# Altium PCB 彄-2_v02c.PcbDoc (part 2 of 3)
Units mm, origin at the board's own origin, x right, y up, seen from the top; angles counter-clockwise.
Board outline 115 x 70 mm, 4 copper layers (Top Layer, Mid-Layer 1, Mid-Layer 2, Bottom Layer), stack 1.49 mm thick; 312 components, 169 nets, 916 pads, 492 vias.
Unrouted connection lines stored in the file: 1.
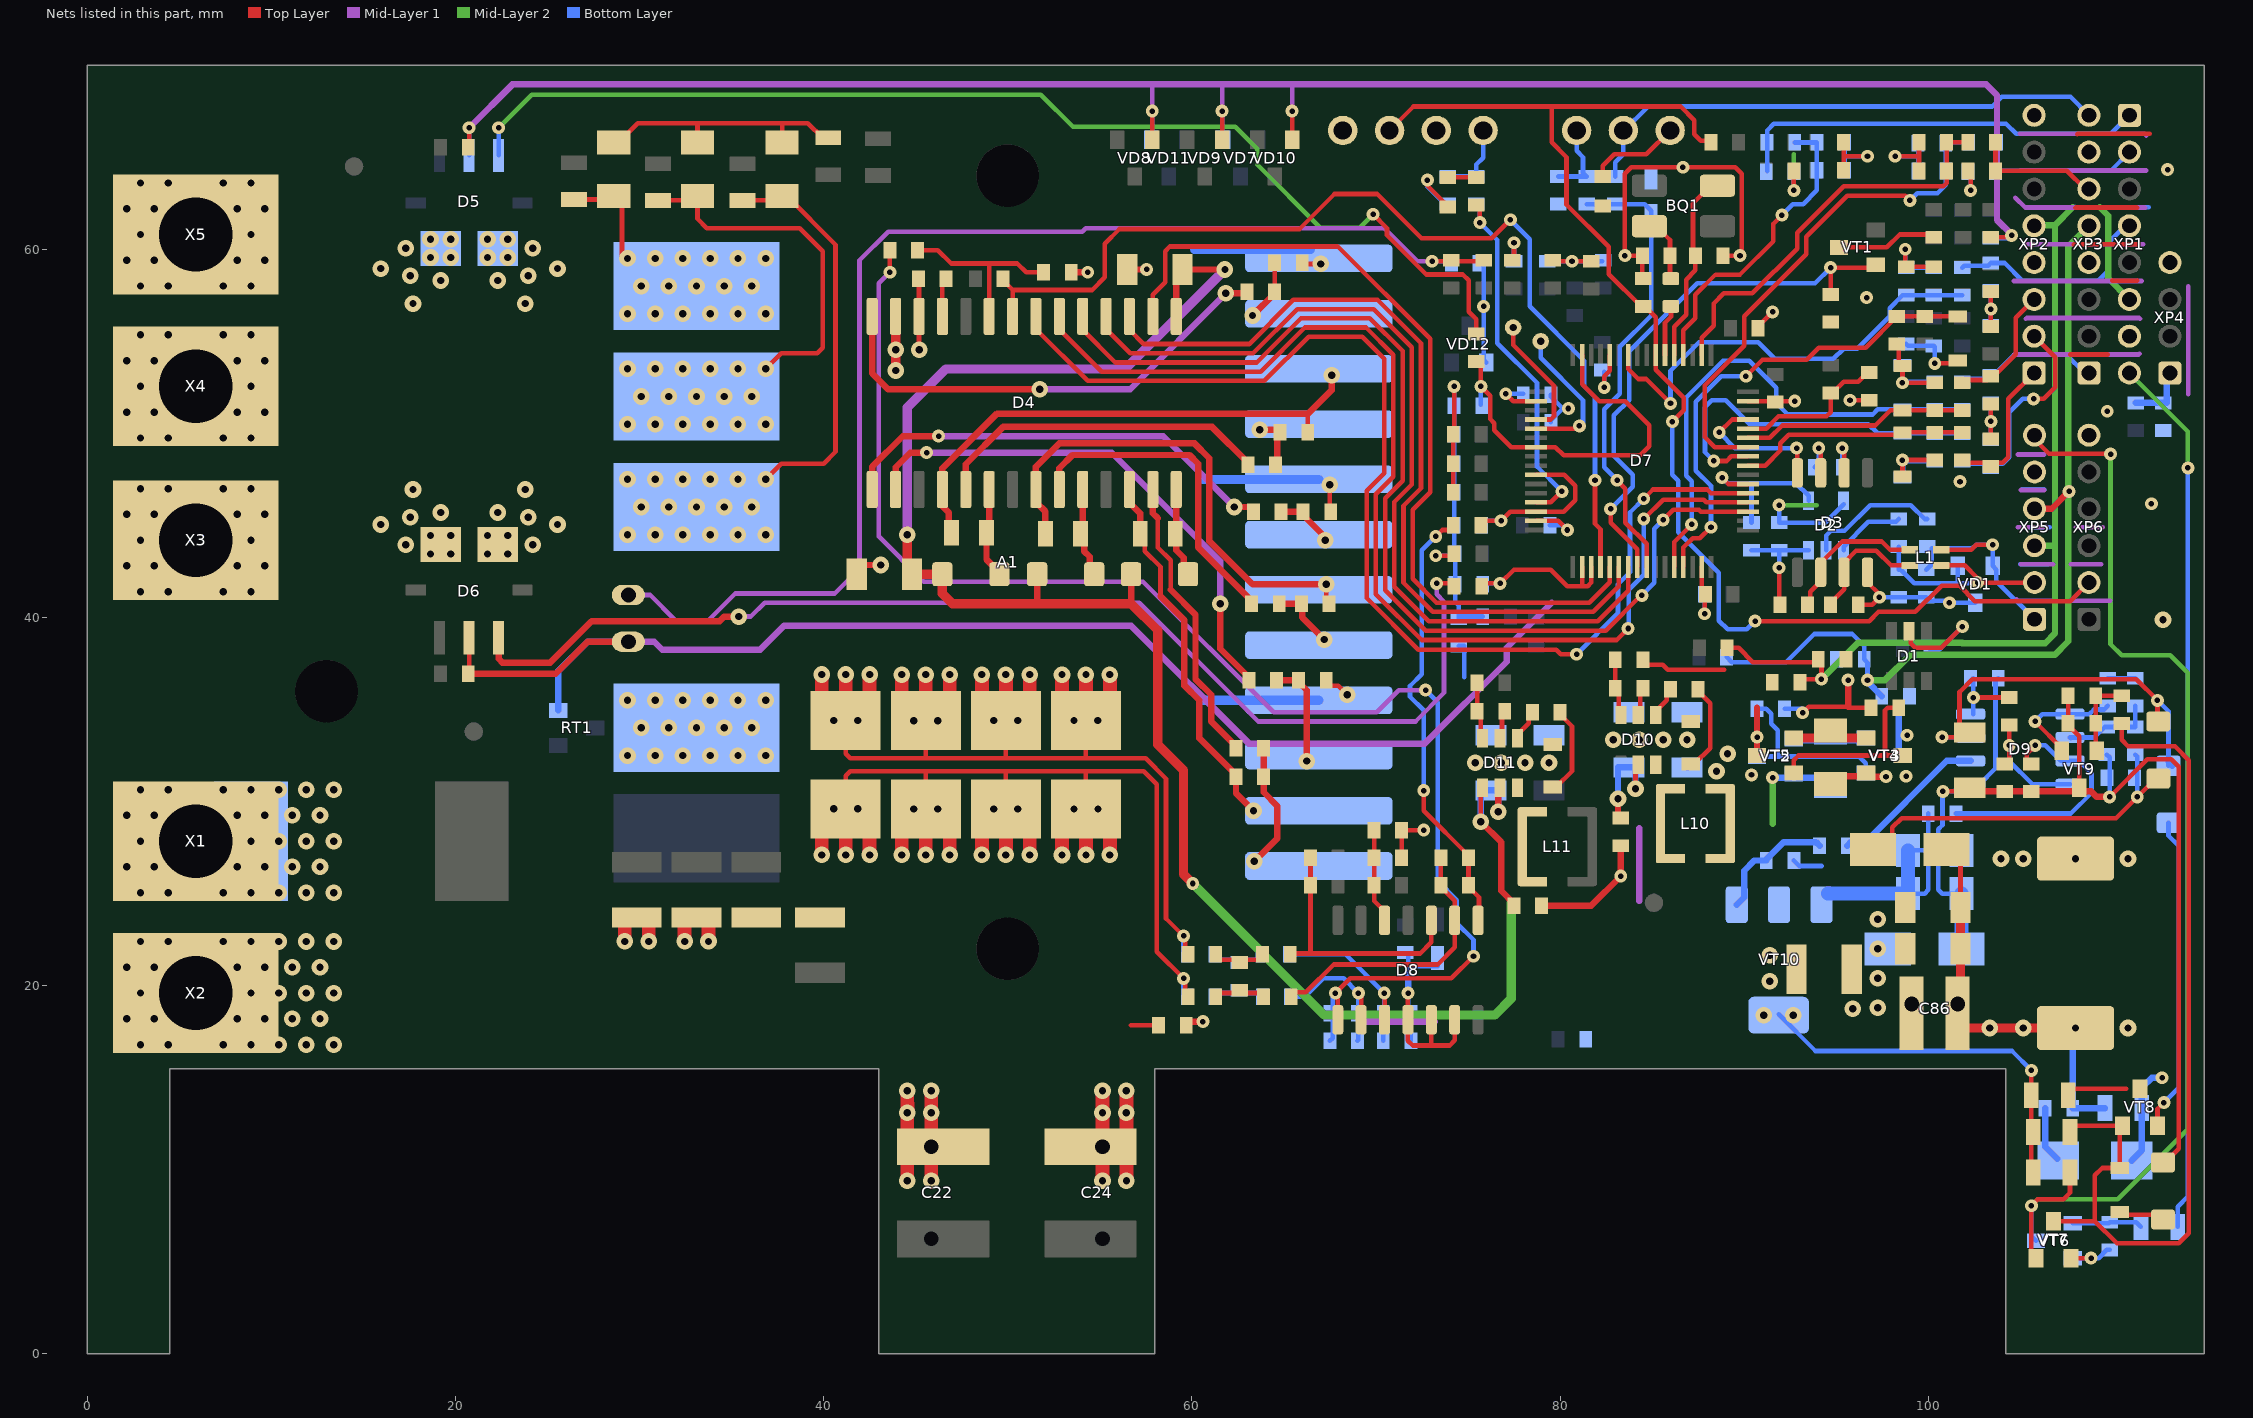
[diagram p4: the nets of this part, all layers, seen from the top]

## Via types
v1: diameter 0.9, hole 0.4, Top Layer to Bottom Layer, 233 vias
v2: diameter 0.7, hole 0.3, Top Layer to Bottom Layer, tented both sides, 184 vias
v3: diameter 0.9, hole 0.4, Top Layer to Bottom Layer, tented both sides, 50 vias
v4: diameter 0.9, hole 0.4, Top Layer to Bottom Layer, tented bottom, 25 vias

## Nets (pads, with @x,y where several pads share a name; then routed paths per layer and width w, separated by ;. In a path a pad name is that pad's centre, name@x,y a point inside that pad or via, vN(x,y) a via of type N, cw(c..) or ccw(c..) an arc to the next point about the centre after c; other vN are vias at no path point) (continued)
5V: C2.2 C3.2 C84.2 D2.5 D3.3 L10.2 R64.1 R65.1 R66.1 R67.1 R68.1 R69.1 R70.1 R91.1 R92.1 R93.1 R94.1 R95.1 R97.1 R126.1 VT3.2 | length 31.2
  Top Layer w0.25: R126.1@84.5,37.7 84.775,37.425 85.575,37.425 85.85,37.15 88.925,37.15 ; v2(92.7,63.2) R64.1@92.7,64.25 ; D3.3@94.16,47.85 v2@94.16,49.19 ; v2(102.3,63.2) R68.1@102.3,64.25 ; R94.1@103.4,49.7 v2(103.4,50.65) R91.1@103.4,51.6 ; R93.1@103.4,55.8 v2(103.4,56.75) R67.1@103.4,57.7
  Top Layer w0.35: R97.1@94.775,30.95 95.2,31.375 96.45,31.375 VT3.2@96.625,31.55 ; VT3.2@96.775,31.35 96.777,31.352 v2(97.705,31.352)
  Mid-Layer 2 w0.25: v2(91.9,46.1) 93.95,46.1 ; v2(92.7,63.2) 92.7,65.15
  Bottom Layer w0.25: v2(91.9,46.1) C2.2@91.9,45.15 94.4,45.15 D2.5@95.4,46.15 ; v2(92.7,63.2) R65.1@92.7,64.2 ; C3.2@93.83,48.15 94.05,48.37 v2(94.05,49.2) ; v2(102.3,63.2) R69.1@102.3,64.2 ; R92.1@103.4,49.65 v2(103.4,50.65) R95.1@103.4,51.65 ; R70.1@103.4,55.85 v2(103.4,56.75) R66.1@103.4,57.75
  Bottom Layer w0.35: C84.2@86.9,31.85 C84.2@86.9,32.2
  other v3: 88.5,31.65 89.1,32.6
12V: C9.2 C10.2 C86.1 C87.2 C88.2 D4.1 L8.1 L9.1 L12.2 R96.1 R128.1 R129.1 VD2.2 VD3.2 VD4.2 VD25.2 VT2.2 | length 128.9
  Top Layer w0.25: VD25.2@101,27.4 101.75,26.65 C87.2@101.75,24.25
  Top Layer w0.35: 51.6,40.75 VD3.2@51.6,42.35 ; 56.7,40.75 VD2.2@56.7,42.35 ; C9.2@59.15,59 C9.2@59.15,58.9 ; D4.1@59.155,56.35 59.155,58.895 C9.2@59.15,58.9 ; v3(61.8,58.9) C9.2@59.5,58.9 C9.2@59.15,58.9 ; L9.1@79,24.35 81.7,24.35 v2(83.3,25.95) L8.1@83.3,27.6
  Top Layer w0.5: C10.2@44.55,42.35 v3(44.55,44.5) ; C10.2@44.8,42.35 VD4.2@46.45,42.35 46.45,41.3 47,40.75 51.6,40.75 56.7,40.75 58.15,39.3 58.15,33.1 59.55,31.7 59.55,26.05 v2(60.05,25.55) ; C87.2@101.75,24.25 C88.2@101.75,22 101.75,18.65 101.6,18.8 C86.1@101.6,18.5 101.6,17.7 v3(103.35,17.7) v3(105.15,17.7) v4(108,17.7)
  Mid-Layer 1 w0.5: v3(44.55,44.5) 44.55,51.4 46.65,53.5 56.4,53.5 v3(61.8,58.9)
  Mid-Layer 2 w0.35: 91.55,28.8 v2(91.55,31.3)
  Mid-Layer 2 w0.5: v2(60.05,25.55) 67.2,18.4 76.45,18.4 77.35,19.3 77.35,24.5
  Bottom Layer w0.35: v2(91.55,31.3) 92.5,31.3 VT2.2@92.7,31.5 92.9,31.3 94.325,31.3 R96.1@94.775,30.85 ; v4@107.85,17.55 R128.1@107.85,13.35 R129.1@109.6,13.35
  other v3: 110.85,17.7
+5VO: C71.2 L6.2 R107.2 XP1.6 XP2.5 XP5.3 | length 54.2
  Top Layer w0.25: R107.2@89.075,38.35 89.7,38.35 90.475,37.575 93.775,37.575 C71.2@93.925,37.725 ; L6.2@93.025,36.475 93.2,36.65 v2(94.2,36.65) 94.2,37.55 C71.2@94.025,37.725
  Mid-Layer 2 w0.25: 107.85,62.275 109.325,62.275
  Mid-Layer 2 w0.35: v2(94.2,36.65) 96.165,38.615 101.835,38.615 101.85,38.6 106.35,38.6 106.885,39.135 106.885,43.9 ; XP5.3@105.775,43.9 106.885,43.9 ; XP2.5@105.785,61.31 106.885,61.31 ; 107.85,62.275 106.885,61.31 ; 109.325,62.275 109.775,61.825 109.775,58.425 XP1.6@110.925,57.275 ; 106.885,43.9 106.885,61.31
+12VO: C70.2 L5.2 R106.2 XP3.5 XP5.4 | length 48.7
  Top Layer w0.35: XP5.4@105.775,45.9 106.7,45.9 v2(107.65,46.85)
  Mid-Layer 2 w0.35: v2(96.7,36.6) 97.65,36.6 99.016,37.966 106.866,37.966 107.6,38.7 107.6,60.15 XP3.5@108.725,61.275
  Bottom Layer w0.25: R106.2@89.05,37.85 89.325,37.575 92.275,37.575 93.8,39.1 95.875,39.1 96.525,38.45 C70.2@96.525,37.725 96.7,37.55 v2(96.7,36.6) v2@96.7,36.5
  Bottom Layer w0.35: v2@96.7,36.5 L5.2@97.475,35.725
\FAULT: D4.8 D7.36 R4.2 | length 54.8
  Top Layer w0.25: R4.2@49.75,58.4 49.75,58.3 50.265,57.785 ; D4.8@50.265,56.35 50.265,57.785 ; v2(77.3,61.6) 76.3,60.6 72.475,60.6 70.075,63 67.75,63 65.85,61.1 56.075,61.1 55.275,60.3 55.275,58.475 54.585,57.785 50.265,57.785 ; v2(81.9,47.45) 81.9,45.1 82.2,44.8 D7.36@82.2,42.75
  Bottom Layer w0.25: v2(77.3,61.6) 78.35,60.55 78.35,56.9 81.3,53.95 81.3,52.557 81.9,51.957 v2(81.9,47.45)
\P_ON: R110.1 VT6.3 VT7.1 XP5.6 | length 63.4
  Top Layer w0.25: XP5.6@105.55,49.9 106.56,48.89 109.885,48.89 v2(109.9,48.875) ; VT7.1@105.85,5.2 105.6,5.45 v2(105.6,8.05) 105.95,8.4 107.35,8.4 107.7,8.75 R110.1@107.7,9.85
  Mid-Layer 2 w0.25: v2(105.6,8.05) 105.95,8.4 110.3,8.4 114.1,12.2 114.1,37 113.15,37.95 110.5,37.95 109.9,38.55 v2(109.9,48.875)
  Bottom Layer w0.25: v2(105.6,8.05) 105.6,6.4 VT6.3@105.85,6.15
\RESET: C37.2 D7.7 R30.1 XP6.2 XV10.1 | length 73.5
  Top Layer w0.25: XV10.1@70.74,66.45 72.04,67.75 79.55,67.75 ; C37.2@84.525,56.9 84.4,56.9 82.65,58.65 82.65,60.125 80.35,62.425 80.35,65 79.55,65.8 79.55,67.75 ; C37.2@84.6,56.9 85.2,56.3 D7.7@85.2,54.25 85.2,53.495 85.2,53.45 86.725,51.925 86.725,51.265 v2(86.1,50.64) 86.08,50.62 v2@86.08,50.64 ; R30.1@88.2,65.9 87.65,65.9 87.3,66.25 87.3,67 86.55,67.75 79.55,67.75 ; v2(90.6,39.8) 96.8,39.8 97.3,40.3 99.3,40.3 100.725,41.725 101.7,41.725 102.535,40.89 107.715,40.89 XP6.2@108.725,41.9
  Bottom Layer w0.25: v2(86.1,50.64) 86.1,47.743 86.425,47.418 86.425,44.625 88.625,42.425 88.625,39.825 89.1,39.35 90.15,39.35 v2(90.6,39.8)
\TMotor-PLUP: D7.40 R63.2 VT1.1 | length 30.4
  Top Layer w0.25: v2(82.75,45.9) 82.75,45.15 84.2,43.7 D7.40@84.2,42.75 ; R63.2@94.7,57.55 v2(94.7,59) 97,59 VT1.1@97.15,59.15
  Bottom Layer w0.25: v2(82.75,45.9) 83.95,47.1 83.95,47.75 82.925,48.775 82.925,50.975 83.75,51.8 83.75,54.45 87.45,58.15 93.85,58.15 v2(94.7,59)
A(+)LED: R27.1 XP3.8 XV8.1 | length 29.2
  Bottom Layer w0.25: R27.1@83,63.95 83,64.725 83.44,65.165 XV8.1@83.44,66.4 ; XV8.1@83.44,66.45 XV8.1@83.44,66.4 ; XP3.8@108.725,67.275 107.725,68.275 104,68.275 103.475,67.75 84.79,67.75 XV8.1@83.44,66.4
ABRAKE-IN: R66.2 R75.1 XP1.4 | length 11.5
  Bottom Layer w0.25: R75.1@101.85,59 101.95,59.1 103.25,59.1 R66.2@103.4,59.25 104.15,59.25 105.115,58.285 109.235,58.285 109.725,58.775 109.725,60.3 XP1.4@110.7,61.275
AGND: C15.1 C16.1 C21.1 C23.1 C33.1 C34.1 C41.2 C42.2 C45.1 C47.1 C48.2 C49.2 C50.2 C51.2 C52.2 C53.2 C54.1 C55.1 C63.1 C64.2 D5.2 D6.2 D7.12 D8.11 D8.12 D8.13 L4.2 R39.1 R43.1 R57.1 R58.1 R59.1 R60.1 R61.1 R62.1 R98.1 RT1.2 RT2.2 VD6.2 VD7.1 VD8.1 VD9.1 VD10.1 VD11.1 VD12.1 | length 237.6
  Top Layer w0.25: C21.1@20.75,37 D6.2@20.75,38.9 ; C16.1@20.75,65.6 v2(20.75,66.6) ; VD8.1@57.85,65.95 v2(57.85,67.5) ; VD9.1@61.65,65.95 v2(61.65,67.5) ; VD10.1@65.45,65.95 v2(65.45,67.5) ; C41.2@71.4,26.95 R39.1@71.4,28.45 v2(72.6,28.45) ; v2@71.74,19.59 D8.11@71.74,18.15 71.74,17.01 72,16.75 73,16.75 ; D8.12@73.01,18.15 73.01,16.76 73,16.75 ; v2(73.25,43.35) R61.1@74.15,43.35 ; R57.1@74.2,46.85 R59.1@74.2,48.35 R98.1@74.2,49.95 74.25,50 v2(74.25,52.55) ; D8.13@74.28,18.15 74.28,17.03 74,16.75 73,16.75 ; R60.1@77.5,59.4 v2(77.5,60.35) ; R62.1@79.6,59.4 79.65,59.35 v2(80.65,59.35) R58.1@81.7,59.35 ; v2(82.4,52.5) 82.4,53.1 82.7,53.4 D7.12@82.7,54.25 ; C55.1@103.4,60.65 104.467,60.65 v2@104.55,60.733
  Top Layer w0.35: C21.1@20.7,36.95 25.45,36.95 27.18,38.68 RT2.2@29.4,38.68
  Mid-Layer 1 w0.25: v2(57.85,67.5) 57.85,68.95 ; v2(61.65,67.5) 61.65,68.95 ; v2(65.45,67.5) 65.45,68.95
  Mid-Layer 1 w0.35: v2(20.75,66.6) 23.1,68.95 57.85,68.95 61.65,68.95 65.45,68.95 103.15,68.95 103.735,68.365 103.735,61.59 104.53,60.795 v2(104.53,60.753) ; RT2.2@29.4,38.68 30.8,38.68 31.23,38.25 36.55,38.25 37.85,39.55 56.703,39.55 63.103,33.15 72.65,33.15 77.1,37.6 77.1,38.35 79.55,40.8
  Bottom Layer w0.25: D5.2@20.75,65.1 v2(20.75,66.6) ; VD11.1@57.85,65.95 v2(57.85,67.5) ; VD7.1@61.65,65.95 v2(61.65,67.5) ; v2(71.75,19.6) 71.75,18.65 C42.2@71.9,18.5 R43.1@71.9,17 ; C47.1@71.75,21.65 71.75,21.05 VD6.2@73.35,21.05 ; v2(73.25,43.35) C52.2@74.2,43.35 ; C52.2@74.25,43.6 C64.2@74.25,49.85 ; C64.2@74.25,49.95 C15.1@74.25,51.5 v2(74.25,52.55) ; C52.2@74.3,43.35 74.3,40.85 74.5,40.65 L4.2@74.5,39.95 74.6,40.05 C34.1@75.8,40.05 ; L4.2@74.5,39.925 L4.2@74.513,39.938 ; VD12.1@75.825,54.025 VD12.1@75.85,54 ; C63.1@75.85,59.15 v2(75.85,56.9) VD12.1@75.85,54 ; VD12.1@76,53.85 VD12.1@75.85,54 ; C51.2@77.4,59.25 C51.2@77.5,59.35 v2(77.5,60.35) ; C53.2@79.3,59.35 v2(80.65,59.35) C48.2@82.3,59.35 ; v2(82.4,52.5) C33.1@82.4,53.35 ; C54.1@103.4,60.6 104.377,60.6 v2(104.53,60.753)
  Bottom Layer w0.35: RT1.2@25.6,34.95 25.6,37.1 27.18,38.68 RT2.2@29.4,38.68 ; v2(71.75,19.6) 71.75,21.05
BOOT0: D7.60 R29.1 R31.1 | length 8.6
  Top Layer w0.25: D7.60@90.2,50.25 91.193,50.25 91.868,50.925 94.475,50.925 94.7,51.15 R29.1@94.7,52.2 ; R29.1@94.6,52.2 R29.1@94.7,52.2 ; R31.1@96.8,53.3 96.7,53.3 96.2,52.8 95.4,52.8 94.8,52.2 R29.1@94.7,52.2
BRAKEA: C61.2 D7.10 R75.2 R86.2 | length 24.2
  Top Layer w0.25: D7.10@83.7,54.25 83.7,53.495 84.243,52.952 84.673,52.952 v2(86,51.625)
  Bottom Layer w0.25: v2(86,51.625) 86,53.4 87.55,54.95 90.76,54.95 91.66,54.05 94.85,54.05 95.4,54.6 96.15,54.6 97.9,56.35 97.9,56.8 98.6,57.5 C61.2@98.8,57.5 R86.2@100.3,57.5 R75.2@101.85,57.5
CAN_H: C8.2 L1.2 R3.2 VD1.1 XP5.2 | length 12.2
  Top Layer w0.25: L1.2@100.7,42.825 101.975,42.825 102.676,42.124 v2(102.676,41.89) 105.54,41.89 XP5.2@105.55,41.9
  Bottom Layer w0.25: R3.2@98.4,43.85 C8.2@98.4,42.6 98.5,42.6 99.25,41.85 101.6,41.85 ; VD1.1@101.6,42.8 101.6,41.85 ; v2@102.676,41.85 101.6,41.85
CAN_L: C7.2 L1.3 R2.2 VD1.2 XP5.1 | length 12.5
  Top Layer w0.25: L1.3@100.7,43.675 102.325,43.675 102.6,43.95 v2(103.5,43.95)
  Bottom Layer w0.25: C7.2@99.9,42.6 100.2,42.9 100.2,43.75 102.4,43.75 102.6,43.95 v2(103.5,43.95) ; v2@103.5,43.925 VD1.2@103.5,42.8 103.7,42.6 103.7,41.975 XP5.1@105.775,39.9
CRUISE: C60.2 D7.4 R73.2 R85.2 | length 16.9
  Top Layer w0.24: D7.4@86.7,54.25 86.7,55.6 87.35,56.25 87.35,57.525 88.45,58.625 89.775,58.625 91.575,60.425 91.575,61.375 v2(92.05,61.85)
  Bottom Layer w0.25: v2(92.05,61.85) 92.65,62.45 93.2,62.45 93.95,63.2 ; R73.2@92.75,65.8 R85.2@93.95,65.8 93.95,63.2
CRUISE-IN: R65.2 R73.1 XP1.1 | length 22.7
  Bottom Layer w0.25: R65.2@91.25,64.25 R73.1@91.25,65.8 91.25,66.45 91.615,66.815 104.225,66.815 104.775,66.265 109.915,66.265 XP1.1@110.925,67.275
DAC1: D7.20 XV5.1 | length 6.9
  Top Layer w0.25: XV5.1@77.35,55.75 XV5.1@77.35,55.85 ; XV5.1@77.45,55.75 77.45,54.8 79.675,52.575 79.675,50.925 79.5,50.75 D7.20@78.7,50.75
DAC2: D7.21 XV6.1 | length 8
  Top Layer w0.25: D7.21@78.7,50.25 80.9,50.25 v2(81.05,50.4)
  Bottom Layer w0.25: XV6.1@78.95,55 78.95,54.1 81.25,51.8 81.25,50.6 v2(81.05,50.4)
DRIVEMODE: C57.2 D7.58 R74.2 R82.2 | length 28.3
  Top Layer w0.25: D7.58@90.2,49.25 88.4,49.25 87.85,49.8 87.85,52.6 90,54.75 90,56.35 93.375,59.725 93.375,60.682 95.593,62.9 98.75,62.9 v2(99,62.65)
  Bottom Layer w0.25: v2(99,62.65) 99.4,63.05 100.5,63.05 100.95,63.5 R82.2@100.95,65.8 ; R82.2@100.95,65.9 R82.2@100.95,65.8 ; R74.2@102.15,65.8 R82.2@100.95,65.8
DRVMODE-IN: R69.2 R74.1 XP1.2 | length 9.3
  Bottom Layer w0.25: R69.2@103.65,64.2 103.65,64.265 R69.2@103.7,64.265 ; R74.1@103.7,65.8 R69.2@103.7,64.265 ; XP1.2@110.925,65.275 109.925,64.275 106.325,64.275 106.315,64.265 R69.2@103.7,64.265
G1B: A1.16 R5.1 R14.1 | length 5.8
  Top Layer w0.35: R5.1@64.6,36.6 R14.1@65.8,36.6 65.8,36.5 66.25,36.05 v3(66.25,32.2)
G1T: A1.18 R8.1 R11.2 | length 7
  Top Layer w0.35: v3(63.4,26.75) 64.65,28 64.65,29.75 63.9,30.5 R11.2@63.9,31.35 R8.1@63.9,32.9
G2B: A1.12 R6.1 R15.1 | length 3.2
  Top Layer w0.35: R6.1@64.85,45.75 R15.1@66.05,45.75 66.05,45.55 67.25,44.35 v3(67.25,44.2)
G2T: A1.14 R9.1 R12.2 | length 3.7
  Top Layer w0.35: R9.1@64.75,40.75 R12.2@65.95,40.75 66,40.7 66,40 v3(67.2,38.8)
G3B: A1.8 R7.1 R16.1 | length 3.4
  Top Layer w0.25: R7.1@64.5,57.7 R16.1@64.5,59.275
  Top Layer w0.35: v3(63.3,56.4) 64.5,57.6 R7.1@64.5,57.7
G3T: A1.10 R10.1 R13.2 | length 3
  Top Layer w0.35: v3(63.7,50.2) 64.65,50.2 R13.2@64.8,50.05 64.65,49.9 64.65,48.4 R10.1@64.55,48.3
GND: C1.1 C2.1 C3.1 C4.1 C5.1 C6.2 C7.1 C8.1 C9.1 C10.1 C11.1 C25.1 C26.1 C27.1 C28.1 C29.1 C30.1 C31.1 C32.1 C35.1 C36.1 C37.1 C46.1 C56.1 C57.1 C58.1 C59.1 C60.1 C61.1 C62.1 C65.1 C66.1 C67.1 C68.1 C69.1 C70.1 C71.1 C74.1 C76.1 C77.1 C84.1 C85.1 C86.2 C87.1 C88.1 D1.2 D2.3 D3.2 D3.8 D4.12 D7.31 D7.47 D7.63 D10.2 D11.2 HL1.1 HL2.1 L4.1 R1.2 R25.2 R31.2 R63.1 R81.1 R82.1 R83.1 R84.1 R85.1 R86.1 R87.1 R104.1 R105.1 R109.1 R124.1 R125.1 R129.2 R130.1 VD1.3 VD5.2 VD13.2 VD14.2 VD15.2 VD16.2 VD17.2 VD22.2 VD23.2 VD24.2 VD26.2 VT6.2 VT7.2 XP1.7 XP2.4 XP2.8 XP3.4 XP3.7 XP4.4 XP5.5 XP6.6 XV4.1 XV7.1 | length 215.9
  Top Layer w0.25: v3@45.185,54.565 D4.12@45.185,56.35 C11.1@45.185,58.4 ; v2(72.8,63.75) 72.8,63.45 73.9,62.35 HL1.1@73.9,62.3 ; D11.2@76.75,33.45 76.85,33.55 76.85,34.75 R125.1@77,34.9 ; D7.31@78.7,45.25 79.9,45.25 v2(80.4,44.75) ; D10.2@84.25,34.7 84.35,34.8 84.35,36 R124.1@84.5,36.15 ; C37.1@84.475,58.45 C36.1@84.475,59.65 v2(83.525,59.65) 83.525,64.1 83.875,64.45 v2(86.675,64.45) 89.525,64.45 89.875,64.1 v2@89.875,59.65 ; C37.1@84.525,58.4 C37.1@84.625,58.5 ; C29.1@87.7,41.45 D7.47@87.7,42.75 ; v2(87.85,40.2) C29.1@87.85,41.2 ; C35.1@88.85,59.65 v2(89.775,59.65) ; D7.63@90.2,51.75 C30.1@91.45,51.75 ; C32.1@90.75,55.7 90.75,55.8 v2(91.55,56.6) ; C30.1@91.5,51.5 C30.1@91.7,51.7 ; C30.1@91.7,51.75 v2(92.75,51.75) ; v2(91.9,42.7) 91.9,40.75 C5.1@91.95,40.7 ; v2(93.175,34.825) 93.5,35.15 95.65,35.15 95.7,35.1 R105.1@96.9,35.1 R105.1@96.9,35 ; C59.1@95.4,64.3 R84.1@95.4,65.8 ; 95.4,65.05 v2(96.7,65.05) ; D3.2@95.43,47.85 v2@95.43,49.18 ; v2(95.75,51.8) R31.2@96.8,51.8 ; C4.1@96.2,40.7 96.95,40.7 v2(97.35,41.1) 97.35,41.25 96.7,41.9 D3.8@96.7,42.45 ; v2(98.2,65.05) 99.5,65.05 ; C68.1@98.3,54.85 98.4,54.75 98.4,53.85 VD17.2@98.6,53.65 ; VD17.2@98.55,53.7 VD17.2@98.6,53.65 ; VD13.2@98.6,47.65 v2(98.6,48.55) C65.1@100.35,48.55 ; R87.1@98.75,59.05 v2(98.75,60) ; R87.1@98.8,59.05 C62.1@100.3,59.05 ; D1.2@98.95,39.25 99.05,39.15 99.05,38.6 99.3,38.35 100.7,38.35 v2(101.85,39.5) ; C56.1@99.5,64.25 R81.1@99.5,65.75 ; C69.1@100.35,52.75 v2(98.6,52.75) VD17.2@98.6,53.65 ; v2(100.35,53.8) 101.45,53.8 VD16.2@101.6,53.95 ; 107.715,54.285 109.735,54.285 109.75,54.3 ; VT7.2@107.75,5.2 v2(108.85,5.2) ; 107.9,60.25 107.915,60.265 111.335,60.265 111.35,60.25 ; 108,62.25 108.015,62.265 111.335,62.265 111.35,62.25 ; 108.1,66.25 108.115,66.265 112.035,66.265 ; 110,58.3 110.015,58.285 111.335,58.285 111.35,58.3
  Top Layer w0.35: C10.1@41.8,42.85 v3(43.1,42.85) ; C46.1@53.45,58.75 v2(54.35,58.75) ; C9.1@56.5,58.9 v2(57.55,58.9) ; R130.1@59.7,18.05 v2(60.6,18.05) ; 95.65,35.15 v2(95.65,36.6)
  Mid-Layer 1 w0.25: 104.65,58.275 111.6,58.275 ; 104.685,54.285 111.435,54.285 111.475,54.325 ; 104.725,62.8 105.26,62.265 111.76,62.265 111.775,62.25 ; 104.8,40.975 104.865,40.91 106.665,40.91 ; 104.86,44.91 106.385,44.91 106.4,44.925 ; 104.875,48.85 106.3,48.85 ; 104.96,66.265 111.76,66.265 111.85,66.175 ; 105.025,42.9 106.775,42.9 ; 105.025,46.925 106.3,46.925 ; 105.025,64.275 111.825,64.275 ; 105.3,56.225 105.34,56.265 111.46,56.265 111.5,56.225 ; 105.3,60.275 111.675,60.275 ; 107.75,42.9 109.4,42.9 ; 107.8,40.9 109.875,40.9 ; 108.025,44.9 109.475,44.9 ; 114.125,52.125 114.125,58
  Mid-Layer 1 w0.35: 69.25,18.05 73.198,18.05 ; 84.3,24.6 84.3,28.548
  Bottom Layer w0.25: v2(72.8,63.75) 72.8,63.4 73.75,62.45 C26.1@73.9,62.45 ; L4.1@74.5,38.45 74.8,38.45 74.8,36.75 ; C28.1@79.45,45 80.15,45 v2(80.4,44.75) ; R25.2@79.5,52.1 79.5,52 v2@80.15,51.35 ; v2(80.45,51.35) v2@80.15,51.35 ; v2(87.85,40.2) C31.1@87.85,41.25 ; R1.2@90.4,43.65 C2.1@91.9,43.65 ; v2(91.9,42.7) C2.1@91.9,43.65 ; R104.1@92.2,35.05 v2@93.175,35.05 ; D2.3@93.5,43.65 C2.1@91.9,43.65 ; C3.1@95.33,48.15 v2@95.33,49.18 ; C60.1@95.45,64.3 95.45,65.05 ; R85.1@95.45,65.8 95.45,65.05 ; v2(96.7,65.05) 95.45,65.05 ; v2(97.35,41.1) C8.1@98.4,41.1 C7.1@99.9,41.1 ; v2(98.2,65.05) 99.45,65.05 ; VD15.2@98.6,47.6 98.65,47.65 98.65,48.5 C67.1@100.35,48.5 ; v2(98.6,52.75) VD14.2@98.6,53.7 ; v2@98.65,52.8 C66.1@100.35,52.8 ; C61.1@98.75,59 v2(98.75,60) ; R83.1@98.8,54.85 98.9,54.75 C58.1@100.3,54.75 100.35,54.7 v2(100.35,53.8) ; C61.1@98.8,59 R86.1@100.3,59 ; C57.1@99.45,64.25 99.45,65.05 ; R82.1@99.45,65.75 99.45,65.05 ; C7.1@99.9,40.9 v2@101.15,40.9 ; C1.1@100.1,38.25 100.6,38.25 v2(101.85,39.5) ; v2(101.15,40.8) VD1.3@102.55,40.8 ; 105,42.9 106.5,42.9 ; 105,44.9 106.6,44.9 ; 105.1,46.95 106.3,46.95 ; VT6.2@107.85,5.2 v2(108.85,5.2) 109.25,5.2 109.7,5.65 R109.1@109.85,5.65 ; 107.95,62.3 107.965,62.285 111.985,62.285 ; C27.1@79.5,50.7 C27.1@79.5,50.6 C27.1@79.5,50.7 ; C27.1@79.5,50.7 v2@80.15,51.35
  Bottom Layer w0.35: VD26.2@111.05,10.5 111.6,11.05 R129.2@111.6,13.35 111.6,14.45 112.15,15 v2(112.7,15)
  other v1: 95.9,18.75 97.25,18.8 97.25,20.4 97.25,22 97.25,23.6
  other v2: 112.125,46.175 101.725,47.375 95.33,49.2 109.725,51.2 96.65,57.375 113,64.325
  other v3: 75.4,32.1 76.8,32.1 78.1,32.1 79.4,32.1 82.9,33.35 84.3,33.35 85.6,33.35 86.9,33.35 112.75,39.875 45.2,54.55
HALL1: C65.2 D7.56 R99.1 VD13.1 | length 12.6
  Top Layer w0.25: D7.56@90.2,48.25 91.15,48.25 91.97,49.07 91.97,49.47 92.425,49.925 98.475,49.925 VD13.1@98.6,50.05 R99.1@101.85,50.05
HALL2: C67.2 D7.57 R100.1 VD15.1 | length 20
  Top Layer w0.25: v2(88.35,48.5) 89.05,48.5 89.3,48.75 D7.57@90.2,48.75
  Bottom Layer w0.25: v2(88.35,48.5) 87.875,48.975 87.875,51.425 88.25,51.8 89,51.8 90.3,50.5 96.75,50.5 97.25,50 VD15.1@98.6,50 R100.1@101.85,50
HALL3: C69.2 D7.59 R101.1 VD17.1 | length 12.3
  Top Layer w0.25: D7.59@90.2,49.75 91.4,49.75 92.075,50.425 97.125,50.425 97.95,51.25 VD17.1@98.6,51.25 R101.1@101.85,51.25
I-DCA: C45.2 D7.26 D7.30 R46.2 | length 10
  Top Layer w0.25: R46.2@75.7,45.05 75.9,45.25 v2(76.8,45.25) 77.3,45.75 D7.30@78.7,45.75 80.2,45.75 80.825,46.375 80.825,47.15 80.225,47.75 D7.26@78.7,47.75
  Bottom Layer w0.25: C45.2@75.75,45.05 75.95,45.25 v2(76.8,45.25)
I_UA: C23.2 D7.34 D7.35 R21.1 | length 9.6
  Top Layer w0.25: R21.1@75.75,41.85 v2(76.75,41.85) 77.5,42.6 79.5,42.6 80.4,41.7 81.5,41.7 81.7,41.9 D7.35@81.7,42.75 ; 81.2,41.7 D7.34@81.2,42.75
  Bottom Layer w0.25: C23.2@75.8,41.85 v2(76.75,41.85)
I_WA: C15.2 D7.15 D7.23 R17.1 | length 21.5
  Top Layer w0.25: R17.1@75.7,53.9 v2(75.7,52.55) 76.2,52.05 76.2,50.78 76.428,50.552 76.428,50.172 77.35,49.25 D7.23@78.7,49.25 79.743,49.25 80.193,48.8 84.35,48.8 84.85,49.3 84.85,50.45 83.55,51.75 82.125,51.75 81.2,52.675 D7.15@81.2,54.25
  Bottom Layer w0.25: C15.2@75.7,51.55 v2(75.7,52.55)
IDCMDRV: C46.2 D4.9 R47.2 | length 10.2
  Top Layer w0.25: R47.2@45.1,59.95 46.2,59.95 46.925,59.225 48.995,59.225 ; D4.9@48.995,56.35 48.995,59.225 ; C46.2@51.95,58.75 51,58.75 50.525,59.225 48.995,59.225
INHALL1: R94.2 R99.2 XP2.1 | length 7.8
  Top Layer w0.25: R99.2@101.85,48.55 102,48.4 104.05,48.4 104.35,48.7 104.35,51.875 XP2.1@105.75,53.275
INHALL2: R92.2 R100.2 XP2.2 | length 11.7
  Top Layer w0.25: XP2.2@105.525,55.275 XP2.2@105.638,55.163 ; v2(105.725,51.875) 106.275,51.875 106.9,52.5 106.9,54.125 XP2.2@105.75,55.275
  Bottom Layer w0.25: R100.2@101.85,48.5 102,48.35 104.05,48.35 104.4,48.7 104.4,51.15 105.125,51.875 v2(105.725,51.875)
INHALL3: R91.2 R101.2 XP2.3 | length 7.1
  Top Layer w0.25: XP2.3@105.75,57.275 104.75,56.275 104.75,54.3 103.55,53.1 R91.2@103.4,53.1 103.2,52.9 R101.2@102,52.9 ; R101.2@102,52.9 R101.2@101.85,52.75 R101.2@102,52.9
L1: A1.4 D6.5 R48.1 R51.1 | length 21.6
  Top Layer w0.25: R51.1@35.6,62.65 R48.1@37.5,62.65 ; v1(36.85,47.5) 37.7,48.35 40,48.35 40.65,49 40.65,60.25 38,62.9 R48.1@37.75,62.9
  other v1: 21.75,43.45 22.85,43.45 24.2,43.95 21.75,44.45 22.85,44.45 29.35,44.5 30.85,44.5 32.35,44.5 33.85,44.5 35.35,44.5 36.85,44.5 25.55,45.05 23.95,45.45 22.3,45.7 30.1,46 31.6,46 33.1,46 34.6,46 36.1,46 23.8,46.95 29.35,47.5 30.85,47.5 32.35,47.5 33.85,47.5 35.35,47.5
L3: A1.6 D5.5 R50.1 R53.1 | length 5.8
  Top Layer w0.25: R53.1@26.45,62.7 29.05,62.7 v1@29.05,59.5
  other v1: 29.35,56.5 30.85,56.5 32.35,56.5 33.85,56.5 35.35,56.5 36.85,56.5 23.8,57.05 30.1,58 31.6,58 33.1,58 34.6,58 36.1,58 22.3,58.3 23.95,58.55 25.55,58.95 29.35,59.5 30.85,59.5 32.35,59.5 33.85,59.5 35.35,59.5 36.85,59.5 21.75,59.55 22.85,59.55 24.2,60.05 21.75,60.55 22.85,60.55
LED1: D7.29 R23.1 R26.2 | length 20
  Top Layer w0.25: v2(75.65,61.45) R26.2@75.65,62.4 ; D7.29@78.7,46.25 79.5,46.25 v2(80.1,46.85)
  Bottom Layer w0.25: R23.1@75.65,62.45 v2(75.65,61.45) 76.6,60.5 76.6,54.9 78.75,52.75 78.75,48.2 v2(80.1,46.85)
LED2: D7.41 R24.1 R27.2 VD5.1 | length 25
  Top Layer w0.25: v2(83.1,47.45) 83.55,47 83.55,45.15 84.7,44 D7.41@84.7,42.75
  Bottom Layer w0.25: R24.1@81.45,62.45 84.6,62.45 84.95,62.1 VD5.1@84.95,61.8 84.95,56.4 83.25,54.7 83.25,52.15 82.4,51.3 82.4,48.15 v2(83.1,47.45)
NetBQ1_2: BQ1.2 C36.2 R28.1 | length 3.5
  Top Layer w0.25: BQ1.2@84.85,61.25 85.225,61.25 85.975,60.5 C36.2@85.975,59.65 R28.1@85.975,58.45
NetC4_2: C4.2 D3.7 L1.1 | length 6.8
  Top Layer w0.25: C4.2@94.7,40.7 94.7,40.8 95.43,41.53 D3.7@95.43,42.45 95.43,42.98 96.075,43.625 97.175,43.625 97.975,42.825 L1.1@99,42.825
NetC5_2: C5.2 D3.6 L1.4 | length 8.1
  Top Layer w0.25: C5.2@93.45,40.7 93.6,40.85 93.6,41.4 94.16,41.96 D3.6@94.16,42.45 94.16,42.96 95.325,44.125 97.475,44.125 97.925,43.675 L1.4@99,43.675
NetC6_1: C6.1 L2.2 XP4.1 | length 3.7
  Bottom Layer w0.35: L2.2@111.275,51.65 C6.1@112.775,51.65 ; C6.1@112.95,51.65 XP4.1@112.95,53.1 ; XP4.1@112.95,53.625 XP4.1@112.95,53.1 ; XP4.1@113.125,53.275 XP4.1@112.95,53.1
NetC11_2: C11.2 D4.11 | length 1.9
  Top Layer w0.25: D4.11@46.455,56.35 C11.2@46.455,58.205
NetC12_2: C12.2 D4.28 VD2.1 | length 4.9
  Top Layer w0.35: D4.28@59.155,46.95 59.155,43.645 59.555,43.245 59.555,42.595 VD2.1@59.8,42.35
NetC13_2: C13.2 D4.24 VD3.1 | length 4.7
  Top Layer w0.35: C13.2@53.95,44.55 54.15,44.35 54.15,43.6 54.45,43.3 VD3.1@54.45,42.35 ; C13.2@54.075,44.675 D4.24@54.075,46.95
NetC14_2: C14.2 D4.20 VD4.1 | length 5
  Top Layer w0.35: D4.20@48.995,46.95 48.995,44.745 C14.2@48.85,44.6 48.85,43.15 49.55,42.45 VD4.1@49.55,42.35
NetC25_2: C25.2 R24.2 XV3.1 | length 4.3
  Bottom Layer w0.25: C25.2@79.9,63.95 R24.2@81.45,63.95 81.25,64.15 81.25,65 80.9,65.35 XV3.1@80.9,66.45
NetC26_2: C26.2 R23.2 XV1.1 | length 4.3
  Bottom Layer w0.25: C26.2@73.9,63.95 75.4,63.95 75.4,64 R23.2@75.45,63.95 75.45,64.6 75.82,64.97 XV1.1@75.82,66.45 ; XV1.1@75.83,66.44 XV1.1@75.84,66.45
NetC38_1: C38.1 R33.2 R37.1 | length 2.8
  Top Layer w0.25: R33.2@61.3,21.7 61.6,21.4 63.55,21.4 R37.1@63.85,21.7
NetC38_2: C38.2 R32.2 R36.1 | length 2.8
  Top Layer w0.25: R32.2@61.3,19.4 61.5,19.6 63.7,19.6 R36.1@63.9,19.4
NetC39_1: C39.1 R35.2 R42.1 | length 2.8
  Bottom Layer w0.25: R35.2@61.25,21.7 61.55,21.4 63.5,21.4 R42.1@63.8,21.7
NetC39_2: C39.2 R34.2 R41.1 | length 2.8
  Bottom Layer w0.25: R34.2@61.25,19.4 61.45,19.6 63.65,19.6 R41.1@63.85,19.4
NetC40_1: C40.1 D8.3 R37.2 R38.2 | length 14.3
  Top Layer w0.25: R37.2@65.35,21.7 65.4,21.75 66.45,21.75 ; R38.2@66.45,26.95 C40.1@66.45,25.45 66.45,21.75 ; D8.3@73.01,23.55 73.01,22.36 72.4,21.75 66.45,21.75
NetC41_1: C41.1 D8.5 R39.2 R40.2 | length 5.1
  Top Layer w0.25: R39.2@69.9,28.45 R40.2@69.9,25.45 69.9,24.6 70.47,24.03 D8.5@70.47,23.55
NetC42_1: C42.1 D8.10 R42.2 R43.2 | length 10.1
  Top Layer w0.25: D8.10@70.47,18.15 v2@70.47,19.58
  Bottom Layer w0.25: R42.2@65.3,21.7 68.35,21.7 v2(70.45,19.6) 70.45,18.55 C42.1@70.4,18.5 R43.2@70.4,17
NetC43_1: C43.1 D8.1 R44.2 R46.1 | length 24.3
  Top Layer w0.25: v2(72.6,30.6) 72.6,29.5 75.03,27.07 C43.1@75.03,26.95 R44.2@75.03,25.45 ; v2(73.25,44.4) 73.6,44.75 73.95,44.75 R46.1@74.2,45 R46.1@74.2,44.85 ; R44.2@74.99,25.41 75.6,24.8 75.6,23.6 D8.1@75.55,23.55
  Bottom Layer w0.25: v2(72.6,30.6) 72.6,34.95 71.85,35.7 71.85,36.275 72.5,36.925 72.5,43.65 v2(73.25,44.4)
NetC43_2: C43.2 D8.2 R36.2 R44.1 | length 15.1
  Top Layer w0.25: R36.2@65.4,19.4 65.65,19.65 66.2,19.65 67.7,21.15 73.35,21.15 74.28,22.08 D8.2@74.28,23.55 74.28,24.62 R44.1@73.55,25.35 ; R44.1@73.53,25.45 C43.2@73.53,26.95
NetC44_1: C44.1 D8.9 R41.2 R45.1 | length 8.6
  Top Layer w0.25: v2(69.05,19.6) 69.2,19.45 D8.9@69.2,18.15
  Bottom Layer w0.25: R41.2@65.35,19.4 66.15,19.4 67.15,20.4 68.25,20.4 v2(69.05,19.6) 69.05,17.05 R45.1@69,17
NetC44_2: C44.2 D8.8 R45.2 R47.1 | length 78
  Top Layer w0.25: v2(43.6,58.75) R47.1@43.6,59.95 ; v2@67.78,19.58 67.93,19.43 D8.8@67.93,18.15 ; v2(67.8,19.6) 68.6,20.4 74.1,20.4 v2(75.3,21.6)
  Mid-Layer 1 w0.25: v2(43.6,58.75) 43,58.15 43,44.4 45.45,41.95 57.35,41.95 64.45,34.85 70.05,34.85 71.25,36.05 v2(72.7,36.05)
  Bottom Layer w0.25: R45.2@67.5,17 67.65,17.15 67.65,19.45 v2(67.8,19.6) ; v2(72.7,36.05) 73.35,35.4 73.35,25.7 74.4,24.65 74.4,23.4 75.3,22.5 v2(75.3,21.6)
NetC63_2: C63.2 R80.1 R90.2 RT2.1 | length 67.7
  Top Layer w0.25: v2(73.05,59.35) 74.1,59.35 R90.2@75.9,59.35
  Mid-Layer 1 w0.25: RT2.1@29.4,41.22 30.58,41.22 31.95,39.85 33.75,39.85 35.2,41.3 40.6,41.3 41.95,42.65 41.95,59.393 43.507,60.95 54.05,60.95 54.25,61.15 70.45,61.15 72.25,59.35 v2(73.05,59.35) v2@73.2,59.35
  Bottom Layer w0.25: v2(73.05,59.35) 74,59.35 C63.2@74.1,59.25
NetC72_1: C72.1 C73.2 C75.1 C78.2 C79.1 C83.2 D9.5 L12.1 R115.2 R120.1 R121.2 R122.2 VD19.1 VD24.1 VT9.3 | length 63.2
  Top Layer w0.25: v2(100.8,30.55) 102.05,30.55 C72.1@102.25,30.75 ; R115.2@107.6,35.75 C78.2@107.6,34.25 107.6,34.15 108.2,33.55 VT9.3@108.2,30.75 ; v2(109.85,30.25) 111.9,32.3 113.2,32.3 113.6,31.9 113.6,11.15 112.85,10.4 VD19.1@112.75,10.4
  Top Layer w0.35: C72.1@102.45,30.55 C79.1@105.6,30.55 108.85,30.55 109.15,30.25 v2(109.85,30.25)
  Bottom Layer w0.25: R121.2@101.8,25 100.75,25 100.55,25.2 100.55,27.35 ; R122.2@101.8,27.35 100.55,27.35 ; C73.2@103.8,36.7 103.65,36.55 103.65,31.8 102.79,30.94 D9.5@102.3,30.94 101.79,30.94 101.4,30.55 v2(100.8,30.55) 100.775,30.525 100.775,28.725 100.55,28.5 100.55,27.35 ; R120.1@109.7,32.55 109.85,32.4 v2(109.85,30.25)
  Bottom Layer w0.75: VD24.1@101.8,22 R121.2@101.8,25 ; R122.2@101.8,26.9 R122.2@101.8,27.35
  other v3: 103.95,26.9 105.15,26.9 110.85,26.9
  other v4: 108,26.9
NetC72_2: C72.2 D9.7 VD20.1 VD21.1 | length 21.5
  Top Layer w0.25: v2(100.75,33.5) 101.7,33.5 101.7,35.95 102.4,36.65 111.3,36.65 v2(112.45,35.5) VD21.1@112.45,34.55
  Bottom Layer w0.25: v2(100.75,33.5) D9.7@102.28,33.5 ; v2(112.45,35.5) 113.05,34.9 113.05,32.15 VD20.1@113.05,31.95
  Bottom Layer w0.35: VD20.1@113.05,32.15 VD20.1@113.25,31.95
NetC73_1: C73.1 D9.8 R114.1 | length 3.9
  Top Layer w0.25: v2(102.45,35.65) R114.1@104.4,35.65
  Bottom Layer w0.25: D9.8@102.45,34.75 v2(102.45,35.65) C73.1@102.45,36.7
NetC74_2: C74.2 L7.2 R110.2 R111.2 R112.1 VT10.2 | length 20.5
  Top Layer w0.25: R110.2@105.6,9.85 R112.1@105.6,14.05 v2(105.6,15.4)
  Bottom Layer w0.25: VT10.2@91.875,18.45 93.875,16.45 104.55,16.45 v2(105.6,15.4)
  other v1: 91.075,18.4 92.675,18.4
  other v3: 91.4,20.25 91.4,21.65
NetC75_2: C75.2 D9.4 R114.2 | length 6.8
  Top Layer w0.25: C75.2@104.4,32.05 v2(104.4,33.05) R114.2@104.4,34.15
  Bottom Layer w0.25: v2(104.4,33.05) 104.4,32.2 105.66,30.94 D9.4@107.7,30.94
NetC76_2: C76.2 D10.5 L8.2 | length 6
  Top Layer w0.25: v3(84.1,30.706) D10.5@84.1,32.006
  Top Layer w0.35: L8.2@83.15,29.25 v3(83.15,30.15)
  Bottom Layer w0.35: v3(83.15,30.15) 83.15,31.856 84.1,31.856 v3(84.1,30.706)
NetC77_2: C77.2 D11.4 D11.5 L9.2 | length 12.3
  Top Layer w0.25: v3(75.7,28.9) D11.4@75.7,30.756
  Top Layer w0.35: v3(75.7,28.9) 76.8,27.8 76.8,25.15 77.5,24.45 L9.2@77.5,24.35 ; v3(76.65,29.456) D11.5@76.65,30.756
  Bottom Layer w0.35: v3(75.7,28.9) 75.7,30.606 76.65,30.606 v3(76.65,29.456)
NetC78_1: C78.1 R113.1 R115.1 VT9.1 | length 4.4
  Top Layer w0.25: VT9.1@109.15,32.75 109.1,32.8 C78.1@109.1,34.25 R115.1@109.1,35.75 R113.1@110.5,35.75
NetC79_2: C79.2 D9.3 R117.2 | length 13.5
  Top Layer w0.25: C79.2@105.35,32.3 105.35,32.6 v2(105.8,33.05)
  Bottom Layer w0.25: R117.2@101.5,29.35 107.75,29.35 108.865,30.465 108.865,31.535 108.19,32.21 D9.3@107.7,32.21 107.19,32.21 106.35,33.05 v2(105.8,33.05)
NetC80_1: C80.1 D9.2 R120.2 R123.2 | length 5
  Bottom Layer w0.25: D9.2@107.73,33.45 D9.2@107.7,33.48 109.03,33.48 109.6,34.05 R120.2@109.7,34.05 R123.2@111.25,34.05 C80.1@111.25,35.2
NetC80_2: C80.2 R118.1 | length 1.5
  Bottom Layer w0.25: R118.1@109.75,36.7 C80.2@111.25,36.7
NetC81_1: C81.1 D10.6 L10.1 VD22.1 | length 4.7
  Top Layer w0.25: VD22.1@87.3,32.05 88.15,32.9 88.15,35.35 87.5,36 C81.1@87.5,36.1
NetC81_2: C81.2 D10.1 | length 1.7
  Top Layer w0.25: D10.1@85.2,34.7 85.2,34.9 85.8,35.5 85.8,35.9 C81.2@86,36.1
NetC82_1: C82.1 D11.6 L11.1 VD23.1 | length 4.7
  Top Layer w0.25: VD23.1@79.8,30.8 80.65,31.65 80.65,34.1 80,34.75 C82.1@80,34.85
NetC82_2: C82.2 D11.1 | length 1.7
  Top Layer w0.25: D11.1@77.7,33.45 77.7,33.65 78.3,34.25 78.3,34.65 C82.2@78.5,34.85
NetC83_1: C83.1 R123.1 VD21.2 VD25.1 | length 20.1
  Top Layer w0.25: VD25.1@97,27.4 98.05,27.4 98.05,28.6 98.55,29.1 110.2,29.1 v2(111.35,30.25) 112.35,31.25 VD21.2@112.5,31.25
  Bottom Layer w0.25: R123.1@111.25,32.55 111.35,32.45 v2(111.35,30.25)
NetD2_1: D2.1 R3.1 | length 3.8
  Bottom Layer w0.25: D2.1@95.4,43.65 95.4,43.85 96.75,45.2 98.25,45.2 R3.1@98.4,45.35
NetD2_2: D2.2 R2.1 | length 7.3
  Bottom Layer w0.25: D2.2@94.45,43.65 94.45,44.45 94.7,44.7 95.45,44.7 96.85,46.1 99.05,46.1 99.8,45.35 R2.1@99.95,45.35
NetD4_14: D4.14 R7.2 | length 26
  Top Layer w0.35: D4.14@42.645,56.35 42.645,53.255 43.5,52.4 v3(51.75,52.4) ; v3(61.85,57.6) 62.9,57.6 R7.2@63,57.7
  Mid-Layer 1 w0.35: v3(51.75,52.4) 56.65,52.4 v3(61.85,57.6)
NetD4_15: D4.15 R6.2 | length 24.2
  Top Layer w0.35: D4.15@42.645,46.95 42.645,48.195 44.3,49.85 v2(46.25,49.85) ; v3(62.3,46) R6.2@63.35,46
  Mid-Layer 1 w0.35: v2(46.25,49.85) 58.45,49.85 v3(62.3,46)
NetD4_16: D4.16 R5.2 | length 28.9
  Top Layer w0.35: D4.16@43.915,46.95 43.915,48.165 44.7,48.95 v2(45.6,48.95) ; v3(61.55,40.75) 61.55,38.3 63.1,36.75 R5.2@63.1,36.6 R5.2@63.1,36.45
  Mid-Layer 1 w0.35: v2(45.6,48.95) 55.65,48.95 61.55,43.05 v3(61.55,40.75)
NetD4_19: D4.19 R10.2 | length 18.4
  Top Layer w0.35: D4.19@47.725,46.95 47.725,48.325 49.75,50.35 61.1,50.35 63.05,48.4 R10.2@63.05,48.3
NetD4_23: D4.23 R9.2 | length 17.8
  Top Layer w0.35: D4.23@52.805,46.95 52.805,48.105 53.525,48.825 59.875,48.825 60.35,48.35 60.35,43.8 R9.2@63.2,40.95
NetD4_27: D4.27 R8.2 | length 15.9
  Top Layer w0.25: 58.15,45.4 58.15,43.8 58.85,43.1 58.85,41.5
  Top Layer w0.35: D4.27@57.885,46.95 57.885,45.665 58.15,45.4 ; 58.85,41.5 60.2,40.15 60.2,36.65 61.05,35.8 61.05,34.35 62.4,33 R8.2@62.4,32.9
NetD5_3: D5.3 R17.2 | length 63.5
  Top Layer w0.25: v2(69.85,61.9) 70.6,61.15 70.6,60.75 72.725,58.625 74.725,58.625 75.035,58.315 75.035,56.615 75.45,56.2 R17.2@75.45,55.4
  Mid-Layer 2 w0.25: v2(22.35,66.6) 24.15,68.4 51.8,68.4 53.55,66.65 62.35,66.65 63.55,65.45 63.55,64.6 66.975,61.175 69.125,61.175 v2(69.85,61.9)
  Bottom Layer w0.25: D5.3@22.35,65.1 v2(22.35,66.6)
NetD6_3: D6.3 R21.2 | length 64.3
  Top Layer w0.25: v2(73.3,41.85) R21.2@74.25,41.85
  Top Layer w0.35: D6.3@22.35,38.9 22.35,37.75 22.55,37.55 25.15,37.55 27.4,39.8 34.35,39.8 34.6,40.05 v3(35.4,40.05)
  Mid-Layer 1 w0.25: v3(35.4,40.05) 36.05,40.05 36.8,40.8 57.15,40.8 63.6,34.35 72.15,34.35 73.7,35.9 73.7,40.85 73.3,41.25 v2(73.3,41.85)
NetD7_18: D7.18 R25.1 | length 2.8
  Top Layer w0.25: v2(77.05,52.15) 77.45,51.75 D7.18@78.7,51.75
  Bottom Layer w0.25: v2(77.05,52.15) R25.1@78,52.15
NetD9_1: D9.1 R118.2 VT9.2 | length 6.5
  Top Layer w0.25: v2(105.8,34.35) 107.25,32.9 VT9.2@107.25,32.75
  Bottom Layer w0.25: v2(105.8,34.35) 106.2,34.75 D9.1@107.7,34.75 108.75,34.75 109,35 109.55,35 R118.2@109.75,35.2
NetD9_6: D9.6 R116.2 | length 8.6
  Bottom Layer w0.35: R116.2@95.6,27.6 95.8,27.8 96.6,27.8 101.01,32.21 D9.6@102.3,32.21
NetD10_3: D10.3 R124.2 R126.2 | length 3.1
  Top Layer w0.25: R126.2@83,37.7 R124.2@83,36.15 83.2,35.95 83.2,34.8 D10.3@83.3,34.7
NetD11_3: D11.3 R125.2 R127.2 | length 3.1
  Top Layer w0.25: R127.2@75.5,36.45 R125.2@75.5,34.9 75.7,34.7 75.7,33.55 D11.3@75.8,33.45
NetFU1_1: FU1.1 X1.1
  other v4: 10.4,25.05 11.9,25.05 13.4,25.05 11.15,26.45 12.65,26.45 10.4,27.85 11.9,27.85 13.4,27.85 11.15,29.25 12.65,29.25 10.4,30.65 11.9,30.65 13.4,30.65
NetHL1_2: HL1.2 R26.1 | length 1.5
  Top Layer w0.25: HL1.2@73.9,63.9 R26.1@75.45,63.9
NetHL2_2: HL2.2 XV9.1 | length 5
  Top Layer w0.25: HL2.2@82.325,63.95 82.325,64.525 82.95,65.15 84.68,65.15 XV9.1@85.98,66.45
NetL5_1: L5.1 VT4.3 | length 2.6
  Bottom Layer w0.35: VT4.3@98.4,32.45 98.4,35.05
  other v2: 98.8,31.375 98.85,33.6
NetL6_1: L6.1 VT5.3 | length 2.6
  Top Layer w0.35: VT5.3@90.7,32.5 90.7,35.1
  other v2: 90.4,31.45 90.7,33.5
NetR48_2: R48.2 R49.2 R50.2 R56.1 | length 14.5
  Top Layer w0.25: R50.2@28.6,65.8 28.85,65.8 29.9,66.85 33.15,66.85 ; R49.2@33.15,65.8 33.15,66.85 ; R48.2@37.75,65.8 37.75,66.85 ; R56.1@40.25,66.05 39.95,66.05 39.15,66.85 37.75,66.85 ; 33.15,66.85 37.75,66.85
NetR78_2: R78.2 VT1.3 | length 5.5
  Top Layer w0.25: VT1.3@95.15,60.1 97.75,60.1 98.45,60.8 100.15,60.8 R78.2@100.3,60.65
NetR96_2: R96.2 VT2.1 VT4.2 | length 3.7
  Bottom Layer w0.5: VT2.1@92.7,33.4 VT4.2@96.4,33.4
NetR97_2: R97.2 VT3.1 VT5.2 | length 3.7
  Top Layer w0.5: VT5.2@92.7,33.45 VT3.1@96.4,33.45
NetR104_2: R104.2 VT2.3 VT4.1 | length 9.9
  Bottom Layer w0.25: VT2.3@90.7,32.45 91.8,32.45 ; R104.2@90.7,35.05 91.2,35.05 91.475,34.775 91.475,34.225 91.825,33.875 91.825,32.475 91.8,32.45 ; VT4.1@96.6,31.55 96.6,32.075 96.225,32.45 91.8,32.45
NetR105_2: R105.2 VT3.3 VT5.1 | length 9.8
  Top Layer w0.25: VT5.1@92.7,31.55 92.7,32.25 92.95,32.5 97.65,32.5 ; VT3.3@98.4,32.5 97.65,32.5 ; R105.2@98.4,35.1 97.8,35.1 97.65,34.95 97.65,32.5
NetR108_1: R108.1 R109.2 VT6.1 | length 3.8
  Bottom Layer w0.25: VT6.1@107.85,7.1 109.8,7.1 R109.2@109.85,7.15 111.3,7.15 R108.1@111.55,6.9
NetR111_1: R111.1 R113.2 VD18.1 VT7.3 VT8.1 | length 48.1
  Top Layer w0.25: VT7.3@106.8,7.2 109.05,7.2 ; R111.1@107.7,12.05 108.05,12.4 VT8.1@110.4,12.4 ; R113.2@110.5,34.25 110.5,33.35 110.85,33 113.4,33 114.15,32.25 114.15,6.55 113.6,6 110.25,6 109.05,7.2 ; VT8.1@110.55,12.4 VT8.1@110.4,12.4 ; 109.05,7.2 109.05,9.7 109.45,10.1 VD18.1@110.4,10.1 VT8.1@110.4,12.4
NetR112_2: R112.2 VT8.3 | length 3.3
  Top Layer w0.25: R112.2@107.6,14.05 107.95,14.4 110.75,14.4
NetR116_1: R116.1 R119.2 VT10.1 | length 6.9
  Bottom Layer w0.35: VT10.1@89.6,24.4 90,24.8 90,26.25 90.55,26.8 R119.2@91.2,26.8 91.2,26.85 92.15,27.8 93.9,27.8 R116.1@94.1,27.6
NetR117_1: R117.1 R119.1 R121.1 R122.1 VT10.3 | length 14.8
  Bottom Layer w0.25: R119.1@92.7,26.8 93,26.5 94.2,26.5 ; R121.1@98.9,25 99.8,25 100,25.2 100,27.35 ; R122.1@98.9,27.35 100,27.35 ; R117.1@100,29.35 100,27.35
  Bottom Layer w0.75: VT10.3@94.55,25 R121.1@98.9,25 R122.1@98.9,27.35
NetR128_2: R128.2 VD26.1 | length 3
  Bottom Layer w0.35: R128.2@106.35,13.35 106.35,11.25 VD26.1@107,10.6
NetVD18_2: VD18.2 VD19.2 | length 2.5
  Top Layer w0.25: VD18.2@110.4,7.7 110.55,7.55 112.5,7.55 VD19.2@112.75,7.3
NetVD20_2: VD20.2 VT8.2 | length 17.2
  Top Layer w0.25: VT8.2@112.45,12.4 112.45,13.3 v2(112.8,13.65)
  Bottom Layer w0.25: v2(112.8,13.65) 113.6,14.45 113.6,27.6 113.05,28.15 VD20.2@113.05,28.85
OSCI: BQ1.4 C35.2 D7.5 | length 10.3
  Top Layer w0.25: D7.5@86.2,54.25 86.2,55.8 86.85,56.45 86.85,58.35 87.35,58.85 C35.2@87.35,59.65 ; C35.2@87.225,59.775 87.225,62.5 88.175,63.45 BQ1.4@88.55,63.45
OSCO: D7.6 R28.2 | length 2.8
  Top Layer w0.25: D7.6@85.7,54.25 85.7,56.007 86.025,56.332 R28.2@86.025,56.9
P_ON: R108.2 XP1.8 | length 47.9
  Mid-Layer 2 w0.25: XP1.8@110.925,53.275 114.1,50.1 v2(114.1,48.125)
  Bottom Layer w0.25: R108.2@113.55,6.9 113.55,8 114.1,8.55 v2(114.1,48.125)
PGND: C17.1 C18.1 C19.1 C20.1 C22.2 C24.2 R18.2 R19.2 R20.2 R22.2 R32.1 R34.1 R130.2 X2.1 | length 104.4
  Top Layer w0.25: R18.2@41.201,29.601 41.201,31.402 41.45,31.651 45.551,31.651 ; R19.2@45.551,29.601 45.551,31.651 ; R20.2@49.901,29.601 49.901,31.651 ; R22.2@54.25,29.6 54.25,31.651 ; 56.7,17.85 R130.2@58.2,17.85 ; R32.1@59.8,19.4 59.65,19.55 59.65,20.3 v2(59.55,20.4) 58.1,21.85 58.1,30.95 57.4,31.651 54.25,31.651 ; 45.551,31.651 49.901,31.651 ; 49.901,31.651 54.25,31.651
  Top Layer w0.75: v1(29.202,22.403) 29.201,23.701 30.502,23.701 v1(30.502,22.403) ; v1@32.451,22.404 32.451,23.701 33.752,23.701 v1(33.752,22.403) ; v1(39.901,27.101) 39.901,28.299 R18.2@41.202,29.6 ; v1(41.202,27.101) 41.201,27.102 R18.2@41.201,29.601 ; v1(42.502,27.101) 42.502,28.3 R18.2@41.201,29.601 ; v1(44.251,27.101) 44.251,28.299 R19.2@45.552,29.6 ; v1(44.55,9.401) C22.2@44.55,11.25 ; v1(44.551,14.299) v1(44.551,14.299) v1(44.551,13.099) 44.55,13.098 C22.2@44.55,11.25 ; v1(45.552,27.101) v1(45.552,27.101) R19.2@45.551,29.601 46.852,28.3 v1(46.852,27.101) ; v1(45.851,9.401) C22.2@45.85,11.25 ; v1(45.851,14.299) v1(45.851,14.299) v1(45.851,13.099) C22.2@45.85,11.25 ; v1(48.601,27.101) 48.601,28.299 R20.2@49.902,29.6 ; v1(49.902,27.101) v1(49.902,27.101) 49.901,29.601 51.202,28.3 v1(51.202,27.101) ; v1(52.951,27.1) 52.951,28.298 R22.2@54.252,29.599 ; v1(54.252,27.1) 54.251,27.101 R22.2@54.25,29.6 55.552,28.299 v1(55.552,27.1) ; v1(55.149,9.401) C24.2@55.15,11.25 ; v1(55.149,14.299) v1(55.149,14.299) v1(55.149,13.099) C24.2@55.15,11.25 ; v1(56.449,14.299) v1(56.449,14.299) v1(56.449,13.099) 56.45,13.098 C24.2@56.45,11.25 ; v1(56.45,9.401) C24.2@56.45,11.25 ; C22.2@44.55,11.25 C22.2@45.85,11.25 ; C24.2@55.15,11.25 C24.2@56.45,11.25
  Bottom Layer w0.25: v2(59.55,20.4) 59.55,19.6 R34.1@59.75,19.4
  other v1: 10.4,16.8 11.9,16.8 13.4,16.8 11.15,18.2 12.65,18.2 10.4,19.6 11.9,19.6 13.4,19.6 11.15,21 12.65,21 10.4,22.4 11.9,22.4 13.4,22.4 32.452,22.403 40.551,29.6 41.851,29.6 44.9,29.6 46.2,29.6 49.252,29.6 50.552,29.6 53.602,29.599 54.902,29.599
PH_A: D6.6 X3.1
  other v1: 18.65,43.45 19.75,43.45 17.3,43.95 18.65,44.45 19.75,44.45 15.95,45.05 17.55,45.45 19.2,45.7 17.7,46.95
PH_B: A1.5 R49.1 R52.1 X4.1 | length 19.8
  Top Layer w0.25: R52.1@31,62.65 R49.1@33.15,62.65 ; R49.1@33.15,62.9 R49.1@33.15,62.65 ; v1(36.85,53.5) 37.7,54.35 39.65,54.35 39.95,54.65 39.95,59.9 38.7,61.15 33.65,61.15 33.15,61.65 R49.1@33.15,62.65
  other v1: 29.35,50.5 30.85,50.5 32.35,50.5 33.85,50.5 35.35,50.5 36.85,50.5 30.1,52 31.6,52 33.1,52 34.6,52 36.1,52 29.35,53.5 30.85,53.5 32.35,53.5 33.85,53.5 35.35,53.5
PH_C: D5.6 X5.1
  other v1: 17.7,57.05 19.2,58.3 17.55,58.55 15.95,58.95 18.65,59.55 19.75,59.55 17.3,60.05 18.65,60.55 19.75,60.55
PWM1H: D4.2 D7.37 | length 46.4
  Top Layer w0.25: D4.2@57.885,56.35 57.885,57.535 58.55,58.2 58.55,59.9 58.8,60.15 67.936,60.15 72.95,55.136 72.95,46.807 72,45.857 72,42.093 73.293,40.8 81.593,40.8 82.7,41.907 82.7,41.995 D7.37@82.7,42.75
PWM1L: D4.5 D7.51 | length 59.2
  Top Layer w0.25: D4.5@54.075,56.35 54.075,55.625 55.85,53.85 63.529,53.85 65.929,56.25 69.671,56.25 71.45,54.471 71.45,47.429 70.5,46.479 70.5,41.471 72.696,39.275 82.475,39.275 v2@84.4,41.2 ; v2(85.6,45.3) 86.15,45.85 87.55,45.85 87.65,45.75 D7.51@90.2,45.75
  Bottom Layer w0.25: v2(84.45,41.2) 85.125,41.875 85.125,44.825 v2(85.6,45.3) v2@85.75,45.45
PWM2H: D4.3 D7.38 | length 46.2
  Top Layer w0.25: D4.3@56.615,56.35 56.615,55.635 57.4,54.85 63.114,54.85 65.514,57.25 70.086,57.25 72.45,54.886 72.45,47.014 71.5,46.064 71.5,41.886 73.086,40.3 81.8,40.3 83.2,41.7 D7.38@83.2,42.75
PWM2L: D4.6 D7.52 | length 62.2
  Top Layer w0.25: D4.6@52.805,56.35 52.805,55.645 55.1,53.35 63.736,53.35 66.136,55.75 69.464,55.75 70.95,54.264 70.95,47.636 70,46.686 70,41.264 72.489,38.775 83.075,38.775 v2(83.7,39.4) ; v2(84.55,45.35) 85.6,46.4 87.8,46.4 87.95,46.25 D7.52@90.2,46.25
  Bottom Layer w0.25: v2@83.725,39.425 83.725,41.5 84.55,42.325 v2(84.55,45.35)
PWM3H: D4.4 D7.39 | length 48.5
  Top Layer w0.25: D4.4@55.345,56.35 55.345,55.655 56.65,54.35 63.322,54.35 65.722,56.75 69.878,56.75 71.95,54.678 71.95,47.222 71,46.272 71,41.678 72.878,39.8 82.05,39.8 83.7,41.45 D7.39@83.7,42.75
PWM3L: D4.7 D7.53 | length 64.2
  Top Layer w0.25: D4.7@51.535,56.35 51.535,55.665 54.35,52.85 63.943,52.85 66.343,55.25 69.257,55.25 70.45,54.057 70.45,47.843 69.5,46.893 69.5,41.057 72.307,38.25 79.8,38.25 80.05,38 v2(80.9,38) ; v2(84.55,46.45) 85.05,46.95 88,46.95 88.2,46.75 D7.53@90.2,46.75
  Bottom Layer w0.25: v2(80.9,38) 83.15,40.25 83.15,41.8 83.8,42.45 83.8,45.7 v2(84.55,46.45)
PWM_IN1: C66.2 D7.44 R102.1 VD14.1 | length 27.4
  Top Layer w0.25: D7.44@86.2,42.75 86.2,44.1 v2(87.15,45.05)
  Bottom Layer w0.25: v2(87.15,45.05) 87.15,47.4 86.85,47.7 86.85,51.949 88.851,53.95 90.275,53.95 91.75,52.475 91.75,51.65 92.375,51.025 96.975,51.025 97.25,51.3 VD14.1@98.6,51.3 R102.1@101.85,51.3
PWM_IN2: C68.2 D7.45 R103.1 VD16.1 | length 26.3
  Top Layer w0.25: D7.45@86.7,42.75 86.7,43.8 87.2,44.3 87.6,44.3 v2(88.2,44.9) ; v2(90.1,53.1) 91,54 93.4,54 94.05,54.65 96.6,54.65 C68.2@98.3,56.35 R103.1@99.8,56.35 VD16.1@101.6,56.35
  Bottom Layer w0.25: v2(88.2,44.9) 88.2,47.15 87.375,47.975 87.375,51.725 88.75,53.1 v2(90.1,53.1)
R_CAN-OFF: D2.4 D7.54 R1.1 | length 9.1
  Top Layer w0.25: v2(88.8,47.6) 89.15,47.25 D7.54@90.2,47.25
  Bottom Layer w0.25: v2(88.8,47.6) 89.1,47.3 90.4,47.3 ; R1.1@90.4,45.15 90.4,47.3 ; D2.4@93.5,46.35 93.5,46.6 92.8,47.3 90.4,47.3
REVERSE: C56.2 D7.2 R72.2 R81.2 | length 22.3
  Top Layer w0.25: D7.2@87.7,54.25 87.7,55.2 88.35,55.85 88.35,57.05 88.9,57.6 90.45,57.6 92.875,60.025 92.875,60.889 95.411,63.425 100.825,63.425 101,63.6 C56.2@101,64.25 ; C56.2@101,64.3 R81.2@101,65.8 R72.2@102.2,65.8
RVRS: R68.2 R72.1 XP3.6 | length 7
  Top Layer w0.25: R72.1@103.65,65.8 R68.2@103.65,64.25 103.665,64.265 107.526,64.265 108.516,63.275 XP3.6@108.725,63.275
RX_CAN: D3.4 D7.61 | length 7.7
  Top Layer w0.25: v2(88.65,50.05) 89.35,50.75 D7.61@90.2,50.75 ; D3.4@92.89,47.85 v2@92.89,49.16
  Bottom Layer w0.25: v2(88.65,50.05) 89.5,49.2 v2(92.85,49.2)
S1T: A1.17 C12.1 D4.26 R11.1 | length 20.2
  Top Layer w0.25: C12.1@57.2,44.55 57.45,44.3 57.45,43.6 58.3,42.75 58.3,41.15
  Top Layer w0.35: D4.26@56.615,46.95 56.615,46.235 57.2,45.65 C12.1@57.2,44.55 ; 58.3,41.15 59.6,39.85 59.6,36.3 60.4,35.5 60.4,33.45 62.4,31.45 R11.1@62.4,31.35 62.4,30.45 v3(63.35,29.5)
S2T: A1.13 C13.1 D4.22 R12.1 | length 27.1
  Top Layer w0.25: v3(67.3,41.8) 67.3,40.9 R12.1@67.45,40.75
  Top Layer w0.35: C13.1@52.05,44.55 52.05,45.75 51.535,46.265 D4.22@51.535,46.95 51.535,48.185 52.8,49.45 60.15,49.45 60.95,48.65 60.95,44.15 63.3,41.8 v3(67.3,41.8)
S3T: A1.9 C14.1 D4.18 R13.1 | length 28.4
  Top Layer w0.25: R13.1@66.3,50.05 66.3,51.05 66.325,51.075
  Top Layer w0.35: C14.1@46.95,44.6 46.8,44.75 46.8,45.7 46.455,46.045 D4.18@46.455,46.95 46.455,48.105 49.425,51.075 66.325,51.075 67.6,52.35 v3(67.6,53.15)
SH+: A1.2 A1.7 A1.11 A1.15 D4.13 R14.2 R15.2 R16.2 R18.1 R19.1 R20.1 R22.1 R33.1 R35.1 | length 97.1
  Top Layer w0.25: R18.1@41.201,34.401 41.201,32.599 41.45,32.35 45.55,32.35 ; R19.1@45.551,34.401 45.55,32.35 ; R20.1@49.9,34.4 49.9,32.35 ; R22.1@54.25,34.4 54.25,32.35 ; R33.1@59.8,21.7 59.65,21.85 59.65,22.6 v2(59.55,22.7) 58.6,23.65 58.6,31.25 57.5,32.35 54.25,32.35 ; R16.2@66,59.275 66.075,59.2 v3(67,59.2) ; R14.2@67.3,36.6 67.6,36.3 67.95,36.3 v3(68.45,35.8) ; R15.2@67.5,45.8 v3(67.5,47.2) ; 45.55,32.35 49.9,32.35 ; 49.9,32.35 54.25,32.35
  Top Layer w0.5: v3(43.915,53.415) v3(43.915,54.55) D4.13@43.915,56.35
  Top Layer w0.75: v1(39.9,36.9) 39.9,35.701 R18.1@41.2,34.401 ; R18.1@41.201,34.401 R18.1@41.201,34.402 ; v1(41.2,36.9) R18.1@41.201,34.402 ; v1(42.501,36.901) 42.501,35.702 R18.1@41.201,34.402 ; v1(44.25,36.899) 44.25,35.7 R19.1@45.551,34.401 ; v1(45.55,36.899) 45.551,34.401 46.851,35.701 v1(46.851,36.9) ; v1(48.6,36.899) 48.6,35.7 R20.1@49.9,34.4 ; R20.1@49.902,34.4 R20.1@49.901,34.401 ; v1@49.901,36.898 R20.1@49.901,34.401 ; v1(51.201,36.9) 51.201,35.701 R20.1@49.901,34.401 ; v1(52.95,36.899) 52.95,35.7 R22.1@54.25,34.4 ; R22.1@54.25,34.4 R22.1@54.251,34.401 ; v1(54.25,36.899) R22.1@54.251,34.401 ; v1(55.551,36.9) 55.551,35.701 R22.1@54.251,34.401
  Bottom Layer w0.25: v2(59.55,22.7) 59.55,21.9 R35.1@59.75,21.7
  Bottom Layer w0.5: 60.15,60 A1.7@66.45,60 ; 60.6,35.5 A1.15@66.9,35.5 ; 60.6,47.5 A1.11@66.9,47.5
  other v1: 29.35,32.5 30.85,32.5 32.35,32.5 33.85,32.5 35.35,32.5 36.85,32.5 30.1,34 31.6,34 33.1,34 34.6,34 36.1,34 40.551,34.401 41.851,34.401 44.901,34.399 46.201,34.399 49.25,34.4 50.55,34.4 53.6,34.4 54.9,34.4 29.35,35.5 30.85,35.5 32.35,35.5 33.85,35.5 35.35,35.5 36.85,35.5 49.9,36.899
SPD1_SIN: R95.2 R102.2 XP3.1 | length 7.7
  Bottom Layer w0.25: R102.2@101.85,52.8 102,52.95 103.2,52.95 R95.2@103.4,53.15 103.55,53.15 104.665,54.265 105.165,54.265 105.175,54.275 107.5,54.275 XP3.1@108.5,53.275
